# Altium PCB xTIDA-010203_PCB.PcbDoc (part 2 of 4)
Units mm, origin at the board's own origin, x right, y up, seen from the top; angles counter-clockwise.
Board outline 200 x 130 mm, 4 copper layers (Top Layer, Signal Layer 1, Signal Layer 2, Bottom Layer), stack 1.588 mm thick; 249 components, 140 nets, 768 pads, 520 vias.
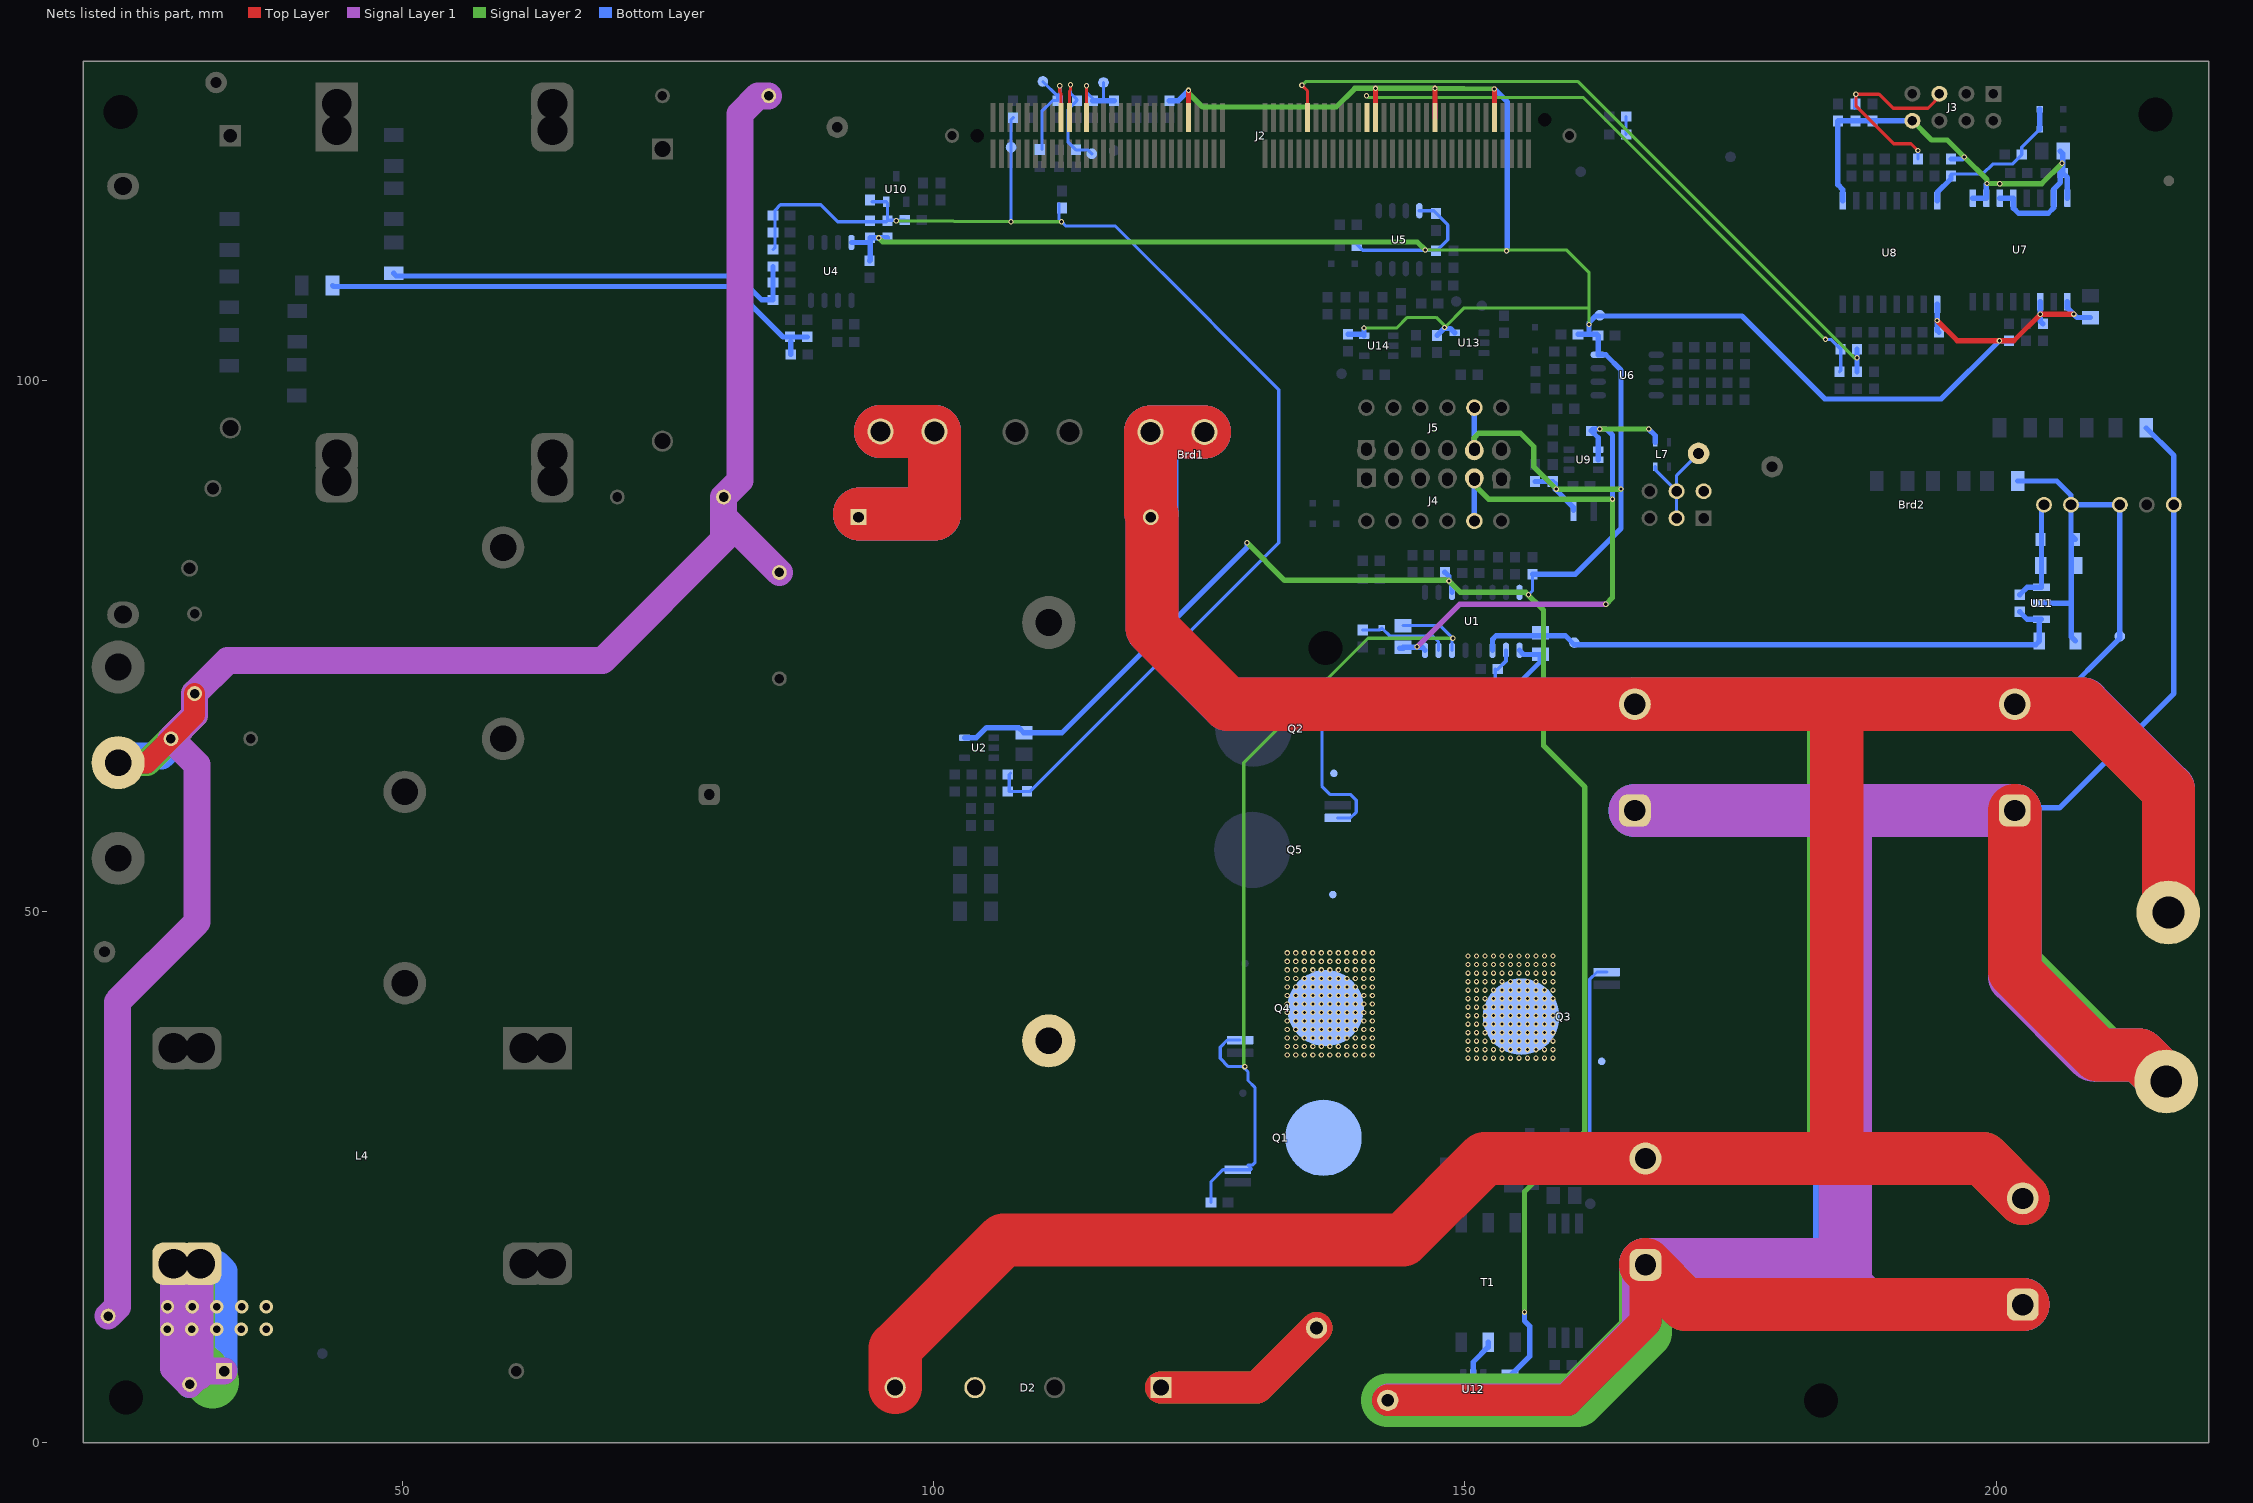
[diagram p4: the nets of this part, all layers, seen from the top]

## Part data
Brd1: library part "Brd- GaN", "GaN daughter card with LMG342xR030", Manufacturer="TEXAS INSTRUMENTS"
Brd2: "60W AuxPower", Manufacturer="Texas Instrument"
C1 C2 C3 C4: library part CMP-0084882-1, "CAP, AL, 680 μF, 450 V, +/- 20%, TH", Cap_Case=35x57mm, Manufacturer=Rubycon, Supplier Part Number 1=1189-2666-ND, Tolerance_%=20%, Value2=450V, ValueDisplayed=680μF
C5: library part CMP-0012436-3, "CAP, Film, 2.2 uF, 630 V, +/- 20%, TH", Manufacturer=Panasonic, Tolerance_%=20%, Value1=Unknown, Value2=630V, ValueDisplayed=2.2uF
C6: library part CMP-0007022-5, "CAP, CERM, 4.7 uF, 35 V, +/- 10%, X5R, 0603", Cap_Case=0603, Manufacturer=TDK, Supplier Part Number 1=445-9064-1-ND, TempCo=X5R, Tolerance_%=10%, Value1="0.003728 ohm", Value2=35V, ValueDisplayed=4.7uF
C7 C14: library part CMP-0009608-4, "CAP, CERM, 330 pF, X1 250 VAC/Y2 300 VAC, +/- 10%, B, TH", Cap_Case=7x5x10mm, Manufacturer=MuRata, Supplier Part Number 1=490-9443-ND, TempCo=B, Tolerance_%=10%, Value1=Unknown, ValueDisplayed=330pF
C8 C9 C13 C15: library part CMP-0009596-2, "CAP, CERM, 1500 pF,  V, +/- 20%, E, D8xT6mm", Cap_Case=8x6x12mm, Manufacturer=TDK, Supplier Part Number 1=445-174536-ND, TempCo=E, Tolerance_%=20%, Value1=Unknown, Value2=V, ValueDisplayed=1500pF
C10 C11 C12: library part CMP-0012433-1, "CAP, Film, 1.2 uF, 630 V, +/- 10%, 0.017 ohm, TH", Manufacturer="Wurth Elktronik", Supplier Part Number 1=495-1886-ND, Tolerance_%=10%, Value1="0.017 ohm", Value2=630V, ValueDisplayed=1.2uF
C16 C26: library part CMP-0007071-1, "CAP, CERM, 22 pF, 50 V, +/- 5%, C0G/NP0, AEC-Q200 Grade 1, 0603", Cap_Case=0603, Manufacturer=TDK, Supplier Part Number 1=445-5632-1-ND, TempCo=C0G/NP0, Tolerance_%=5%, Value1=Unknown, Value2=50V, ValueDisplayed=22pF
C17 C22 C25 C48 C51: library part CMP-0008378-2, "CAP, CERM, 10 uF, 25 V, +/- 10%, X5R, 0805", Cap_Case=0805, Manufacturer=MuRata, Supplier Part Number 1=490-10748-2-ND, TempCo=X5R, Tolerance_%=10%, Value1=Unknown, Value2=25V, ValueDisplayed=10uF
C18: library part CMP-0006942-1, "CAP, CERM, 4700 pF, 50 V, +/- 5%, X7R, 0603", Cap_Case=0603, Manufacturer=Kemet, Supplier Part Number 1=399-1088-1-ND, TempCo=X7R, Tolerance_%=5%, Value1=Unknown, Value2=50V, ValueDisplayed=4700pF
C19: library part CMP-0008378-1, "CAP, CERM, 10 uF, 25 V, +/- 10%, X7R, 0805", Cap_Case=0805, Manufacturer=MuRata, Supplier Part Number 1=81-GRM21BZ71E106KE5L, TempCo=X7R, Tolerance_%=10%, Value1=Unknown, Value2=25V, ValueDisplayed=10uF
C20 C21 C27: library part CMP-0007432-5, "CAP, CERM, 1000 pF, 50 V, +/- 10%, X7R, 0603", Cap_Case=0603, Manufacturer=MuRata, Supplier Part Number 1=490-5768-2-ND, TempCo=X7R, Tolerance_%=10%, Value1=Unknown, Value2=50V, ValueDisplayed=1000pF
C23 C29: "CAP, CERM, 0.01uF, 50V, +/-10%, X7R, 0603", Cap_Case=0603, Manufacturer=Kemet, Supplier Part Number 1=399-5346-1-ND, TempCo=X7R, Tolerance_%=10, Value1=Unknown, Value2=50V, ValueDisplayed=0.01μF
C24 C32 C34 C35 C40 C46 C47 C49 C50 C64 C65 C66 C68: "CAP, CERM, 0.1 μF, 25 V,+/- 10%, X7R, 0603", Cap_Case=0603, Manufacturer=MuRata, Supplier Part Number 1=490-1524-1-ND, TempCo=X7R, Tolerance_%=10, Value2=25V, ValueDisplayed=0.1μF
C28 C59: "CAP, CERM, 1uF, 6.3V, +/-10%, X5R, 0603", Cap_Case=0603, Manufacturer=MuRata, Supplier Part Number 1=81-GRM185R60J105KE26, TempCo=X5R, Tolerance_%=10, Value1=Unknown, Value2=6.3V, ValueDisplayed=1μF
C30 C31 C33 C36 C37 C39 C42 C43: "CAP, CERM, 1000 pF, 50 V,+/- 10%, X7R, 0603", Cap_Case=0603, Manufacturer=MuRata, Supplier Part Number 1=490-1494-1-ND, TempCo=X7R, Tolerance_%=10, Value2=50V, ValueDisplayed=1000pF
C38: library part CMP-0007455-4, "CAP, CERM, 470 pF, 50 V, +/- 10%, X7R, 0603", Cap_Case=0603, Manufacturer=MuRata, Supplier Part Number 1=490-1489-1-ND, TempCo=X7R, Tolerance_%=10%, Value1=Unknown, Value2=50V, ValueDisplayed=470pF
C41 C45: library part GRM188R71E104KA01D, "CAP, CERM, 0.1 μF, 25 V,+/- 10%, X7R, 0603", Cap_Case=0603, Manufacturer=MuRata, Supplier Part Number 1=490-1524-1-ND, TempCo=X7R, Tolerance_%=10, Value2=25V
C44: library part CMP-0007346-2, "CAP, CERM, 0.47 uF, 25 V, +/- 10%, X5R, 0603", Cap_Case=0603, Manufacturer=MuRata, Supplier Part Number 1=GRM188R61E474KA12D-ND, TempCo=X5R, Tolerance_%=10%, Value1=Unknown, Value2=25V, ValueDisplayed=0.47uF
C52 C53: library part CMP-0007433-4, "CAP, CERM, 0.01 uF, 50 V, +/- 10%, X7R, 0603", Cap_Case=0603, Manufacturer=MuRata, Supplier Part Number 1=490-1512-1-ND, TempCo=X7R, Tolerance_%=10%, Value1=Unknown, Value2=50V, ValueDisplayed=0.01uF
C54 C55: "CAP, CERM, 1uF, 25V, +/-10%, X7R, 0603", Cap_Case=0603, Manufacturer=TDK, Supplier Part Number 1=445-5956-1-ND, TempCo=X7R, Tolerance_%=10, Value1=Unknown, Value2=25V, ValueDisplayed=1uF
C56: library part CMP-0007039-5, "CAP, CERM, 0.1 uF, 25 V, +/- 10%, X7R, 0603", Cap_Case=0603, Manufacturer=TDK, Supplier Part Number 1=445-1316-1-ND, TempCo=X7R, Tolerance_%=10%, Value1=Unknown, Value2=25V, ValueDisplayed=0.1uF
C57 C62 C63: library part CMP-0007005-1, "CAP, CERM, 22 uF, 10 V, +/- 20%, X5R, 0603", Cap_Case=0603, Manufacturer=TDK, Supplier Part Number 1=445-9077-1-ND, TempCo=X5R, Tolerance_%=20%, Value1="0.00371 ohm", Value2=10V, ValueDisplayed=22uF
C58: library part CMP-0007347-1, "CAP, CERM, 4.7 uF, 25 V, +/- 10%, X5R, 0603", Cap_Case=0603, Manufacturer=MuRata, Supplier Part Number 1=490-7203-1-ND, TempCo=X5R, Tolerance_%=10%, Value1=Unknown, Value2=25V, ValueDisplayed=4.7uF
C60 C61: library part CMP-0008655-2, "CAP, CERM, 33 uF, 25 V, +/- 20%, X5R, 1206", Cap_Case=1206_180, Manufacturer=TDK, Supplier Part Number 1=445-8046-1-ND, TempCo=X5R, Tolerance_%=20%, Value1="0.002648 ohm", Value2=25V, ValueDisplayed=33uF
C67: library part CMP-0008020-2, "CAP, CERM, 4.7 uF, 16 V, +/- 10%, X7R, AEC-Q200 Grade 1, 0805", Cap_Case=0805, Manufacturer=MuRata, Supplier Part Number 1=490-5332-1-ND, TempCo=X7R, Tolerance_%=10%, Value1=Unknown, Value2=16V, ValueDisplayed=4.7uF
D1 D3 D4 D5 D6 D7 D9 D10: library part BAS316,115, "Diode, Ultrafast, 100 V, 0.25 A, SOD-323", Manufacturer=Toshiba, Value1=0.25A, Value2=1.4V
D2: "Diode, Switching-Bridge, 800 V, 25 A, TH", Manufacturer=Shindengen, Supplier Part Number 1=627-D25XB60-7000, Value1=3.5A, Value2=1.05V
D8: library part CMP-0005747-4, "Diode, Zener, 18 V, 700 mW, SOD-123", Manufacturer=Toshiba, Power_W=700mW, Value1=0.7W
D15: library part CMP-0089345-2, "Bridge Rectifier Single Phase Schottky 30V Surface Mount MBS", Digikey Part Number=1655-1883-1-ND, Forward Current=2A, Manufacturer=SMC, Max Surge Forward Current=50A, Operating Temperature Range="-55°C to +150°C", Peak Reverse Current=0.1mA, ValueDisplayed=28pF
D16: library part CMP-0005769-2, "Diode, Zener, 16 V, 500 mW, AEC-Q101, SOD-123", Manufacturer="Diodes Inc.", Power_W=500mW, Supplier Part Number 1=BZT52C16-FDICT-ND, Value1=0.5W
F1: "Fuse, 20 A, 250 VAC, 60 VDC, TH", Irating_A=20A, Manufacturer=Littelfuse, Supplier Part Number 1=F3336-ND
FID1 FID2 FID3: library part CMP-0077181-1, "Fiducial mark.  There is nothing to buy or mount.", Manufacturer=N/A
H1 H2 H9 H10 H11: library part CMP-0003617-1, "Machine Screw, Round, #4-40 x 1/4, Nylon, Philips panhead", Manufacturer="B&F Fastener Supply", Supplier Part Number 1=H542-ND
H5 H6 H12 H13: library part CMP-0003610-1, "Standoff, Hex, 0.5\"L #4-40 Nylon", Manufacturer=Keystone, Supplier Part Number 1=36-1902C-ND
J2: library part controlCARD-120HSEC, "C2000 controlCARD-120HSEC connector, SMT", Manufacturer=Samtec
J3: "Header, 4-Pin, Dual row,2.54mm", Manufacturer=Any
J4 J5: "Receptacle, 2.54mm, 6x1, Gold, TH", Color=Black, Manufacturer=Molex, Supplier Part Number 1=WM18605-ND
L1: library part CHOKE_PQ35, "PFC CHOKE 480uH 33A", Manufacturer=Sunlord
L2 L5: "DM CHOKE", Manufacturer=Sunlord
L3: library part INDUCTOR_COUPLED_14_23, "Coupled inductor, 2x 1.01 mH, 2 x 0.0022ohm, 1650V TH", Manufacturer=Sunlord, ValueDisplayed=1mH
L4: library part CMP-0013122-2, "Coupled inductor, 2x 1.6 mH, 2 x 0.0022ohm, 1650V TH", Manufacturer=Sunlord, ValueDisplayed=1.6mH
L6: library part CMP-0063086-1, "Inductor, Wirewound, Ferrite, 10 uH, 0.68 A, 0.46 ohm, SMD", Manufacturer="Würth Elektronik", Value1="0.843 ohm", Value2=0.6A, ValueDisplayed=10uH
L7: "Coupled inductor, 0.2 A, 0.45 ohm, SMD", Manufacturer=TDK, Supplier Part Number 1=445-8930-1-ND
LBL1: library part CMP-0003625-1, "Thermal Transfer Printable Labels, 0.650\" W x 0.200\" H - 10,000 per roll", Manufacturer=Brady, Supplier Part Number 1=97C5133
Logo1: library part CMP-0074838-1, "Texas Instrument Corporate Signature"
LOGO2 LOGO4: library part CMP-0074837-1, "IEC 61010-1 Hot Surface Warning"
LOGO3 LOGO5: library part CMP-0074835-1, "IEC 61010-1 High Voltage Warning"
Logo6: library part CMP-0074847-1, "FCC_disclaimer"
Logo7: library part CMP-0074769-1
Logo8: library part CMP-0074844-1
Q1 Q2 Q4 Q5: library part CMP-0086487-1, "MOSFET N-CH 600V 67A 8HSOF", Manufacturer=Infineon
Q3: library part CMP-0086487-1, "MOSFET N-CH 650V 23A HSOF-8", Manufacturer=Infineon
R1 R3 R5 R6 R7 R8 R9 R10 R11 R22 R23 R24: library part CMP-0017798-2, "RES SMD 1M OHM 1% 1/4W 1206", Manufacturer="Vishay Dale", Power_W=250mW, Supplier Part Number 1=BC2834CT-ND, TempCo="100 ppm/C", Tolerance_%=1%, Value2=0.25W, Value_Code=1M00, ValueDisplayed=1.00M
R2 R12: library part CMP-0022735-5, "RES, 100 k, 1%, 0.1 W, 0603", Manufacturer=Yageo, Power_W=100mW, Supplier Part Number 1=311-100KHRCT-ND, TempCo="100 ppm/C", Tolerance_%=1%, Value2=0.1W, Value_Code=100k
R4 R13 R74 R75 R76 R99 R100 R101 R102 R103 R104 R105: library part CMP-0023198-5, "RES, 100R, 1%, 0.1 W, 0603", Manufacturer=Yageo, Power_W=100mW, TempCo="100 ppm/C", Tolerance_%=1%, Value2=0.1W, Value_Code=100R
R14 R16 R31 R64: library part CMP-0022684-3, "RES, 10.0 k, 1%, 0.1 W, 0603", Manufacturer=Panasonic, Power_W=100mW, Supplier Part Number 1=P10.0KHCT-ND, TempCo="100 ppm/C", Tolerance_%=1%, Value2=0.1W, Value_Code=10k0, ValueDisplayed=10.0k
R15 R17 R18: library part CRCW1206330KJNEA, "RES SMD 330K OHM 1% 1/4W 1206", Manufacturer=Yageo, Power_W=0.25, Supplier Part Number 1=RV1206FR-07330KL-ND, TempCo="200 ppm/C", Tolerance_%=5, Value1=5%, Value2=0.25W, Value_Code=330k
R19 R20 R21: library part CMP-0018570-2, "RES, 0.01, 1%, 1 W, 1206", Manufacturer=Vishay-Dale, Power_W=1W, Supplier Part Number 1=WSLP-.01CT-ND, TempCo="75 ppm/C", Tolerance_%=1%, Value_Code=R010, ValueDisplayed=0.01
R25 R36 R39 R41 R43 R44 R69 R70: "RES, 10.0 k, 1%, 0.1 W, 0603", Manufacturer=Vishay-Dale, Power_W=0.1, Supplier Part Number 1=541-10.0KHCT-ND, TempCo="100 ppm/C", Tolerance_%=1, Value1=1%, Value2=0.1W, Value_Code=10k0, ValueDisplayed=10.0k
R26 R27 R29 R30 R42 R48 R54 R60 R66 R78 R93 R94 R95: library part CMP-0022680-4, "RES, 1.00 k, 1%, 0.1 W, 0603", Manufacturer=Panasonic, Power_W=100mW, Supplier Part Number 1=P1.00KHCT-ND, TempCo="100 ppm/C", Tolerance_%=1%, Value2=0.1W, Value_Code=1k00, ValueDisplayed=1.00k
R28: "RES, 50, 1%, 0.1 W, 0603", Manufacturer=Vishay-Dale, Power_W=0.1, Supplier Part Number 1=89M6778, TempCo="100 ppm/C", Tolerance_%=1, Value1=1%, Value2=0.1W, Value_Code=50R0, ValueDisplayed=50
R32: library part CMP-0023168-5, "RES, 51.1, 1%, 0.1 W, 0603", Manufacturer=Yageo, Power_W=100mW, Supplier Part Number 1=311-51.1HRCT-ND, TempCo="100 ppm/C", Tolerance_%=1%, Value2=0.1W, Value_Code=51R1, ValueDisplayed=51.1
R33 R91: library part CMP-0022632-1, "RES, 88.7 k, 1%, 0.1 W, 0603", Manufacturer=Vishay-Dale, Power_W=100mW, Supplier Part Number 1=541-88.7KHCT-ND, TempCo="100 ppm/C", Tolerance_%=1%, Value2=0.1W, Value_Code=88k7, ValueDisplayed=88.7k
R35 R77 R83 R84 R85 R88 R89 R90: library part CMP-0023334-5, "RES, 9.31 k, 1%, 0.1 W, 0603", Manufacturer=Yageo, Power_W=100mW, Supplier Part Number 1=311-9.31KHRCT-ND, TempCo="100 ppm/C", Tolerance_%=1%, Value2=0.1W, Value_Code=9k31, ValueDisplayed=9.31k
R37: library part CMP-0023166-5, "RES, 51.1 k, 1%, 0.1 W, 0603", Manufacturer=Yageo, Power_W=100mW, Supplier Part Number 1=311-51.1KHRCT-ND, TempCo="100 ppm/C", Tolerance_%=1%, Value2=0.1W, Value_Code=51k1, ValueDisplayed=51.1k
R40 R45: library part CMP-0022692-1, "RES, 22.0 k, 1%, 0.1 W, AEC-Q200 Grade 0, 0603", Manufacturer=Panasonic, Power_W=100mW, Supplier Part Number 1=P22.0KHCT-ND, TempCo="100 ppm/C", Tolerance_%=1%, Value2=0.1W, Value_Code=22k0, ValueDisplayed=22.0k
R46: library part CMP-0023148-5, "RES, 4.30 k, 1%, 0.1 W, 0603", Manufacturer=Yageo, Power_W=100mW, Supplier Part Number 1=311-4.30KHRCT-ND, TempCo="100 ppm/C", Tolerance_%=1%, Value2=0.1W, Value_Code=4k30, ValueDisplayed=4.30k
R47: library part CMP-0022708-3, "RES, 7.50 k, 1%, 0.1 W, 0603", Manufacturer=Panasonic, Power_W=100mW, Supplier Part Number 1=P7.50KHCT-ND, TempCo="100 ppm/C", Tolerance_%=1%, Value2=0.1W, Value_Code=7k50, ValueDisplayed=7.50k
R49: "RES, 21.5k ohm, 1%, 0.1W, 0603", Manufacturer=Vishay-Dale, Power_W=0.1, Supplier Part Number 1=541-21.5KHCT-ND, TempCo="100 ppm/C", Tolerance_%=1, Value1=1%, Value2=0.1W, Value_Code=21k5
R50: library part CMP-0022680-4, "RES, 100 k, 1%, 0.1 W, 0603", Manufacturer=Panasonic, Power_W=100mW, TempCo="100 ppm/C", Tolerance_%=1%, Value2=0.1W
R52 R55 R61 R63: library part CMP-0022109-3, "RES, 1.00 k, 1%, 0.1 W, 0603", Manufacturer=Vishay-Dale, Power_W=100mW, Supplier Part Number 1=541-1.00KHCT-ND, TempCo="100 ppm/C", Tolerance_%=1%, Value2=0.1W, Value_Code=1k00, ValueDisplayed=1.00k
R53 R62: "RES, 43.0 k, 1%, 0.1 W, 0603", Manufacturer="Yageo America", Power_W=0.1, Supplier Part Number 1=311-43.0KHRCT-ND, TempCo="200 ppm/C", Tolerance_%=1, Value1=1%, Value2=0.1W, Value_Code=43k0, ValueDisplayed=43.0k
R57: library part CMP-0023108-4, "RES, 430 k, 1%, 0.1 W, 0603", Manufacturer=Yageo, Power_W=100mW, Supplier Part Number 1=311-430KHRCT-ND, TempCo="100 ppm/C", Tolerance_%=1%, Value2=0.1W, Value_Code=430k
R58 R68: library part CMP-0022680-4, "RES, 2.2 k, 1%, 0.1 W, 0603", Manufacturer=Panasonic, Power_W=100mW, TempCo="100 ppm/C", Tolerance_%=1%, Value2=0.1W, Value_Code=2k2
R65: library part CMP-0022906-5, "RES, 20.0 k, 1%, 0.1 W, 0603", Manufacturer=Yageo, Power_W=100mW, Supplier Part Number 1=311-20.0KHRCT-ND, TempCo="100 ppm/C", Tolerance_%=1%, Value2=0.1W, Value_Code=20k0, ValueDisplayed=20.0k
R71: library part CMP-0023198-5, "RES, 0, 1%, 0.1 W, 0603", Manufacturer=Yageo, Power_W=100mW, TempCo="100 ppm/C", Tolerance_%=1%, Value2=0.1W, Value_Code=0, ValueDisplayed=0R
R72 R79 R80 R81 R82 R86 R87: library part CMP-0023198-5, "RES, 5.10 k, 1%, 0.1 W, 0603", Manufacturer=Yageo, Power_W=100mW, Supplier Part Number 1=311-5.10KHRCT-ND, TempCo="100 ppm/C", Tolerance_%=1%, Value2=0.1W, Value_Code=5k10, ValueDisplayed=5.10k
R73: library part CMP-0023198-5, "RES, 100 k, 1%, 0.1 W, 0603", Manufacturer=Yageo, Power_W=100mW, TempCo="100 ppm/C", Tolerance_%=1%, Value2=0.1W, Value_Code=100k
R92: library part CMP-0022220-1, "RES, 22.1 k, 1%, 0.1 W, 0603", Manufacturer=Vishay-Dale, Power_W=100mW, Supplier Part Number 1=541-22.1KHCT-ND, TempCo="100 ppm/C", Tolerance_%=1%, Value2=0.1W, Value_Code=22k1, ValueDisplayed=22.1k
R96: library part CMP-0023309-5, "RES, 8.45 k, 1%, 0.1 W, 0603", Manufacturer=Yageo, Power_W=100mW, Supplier Part Number 1=311-8.45KHRCT-ND, TempCo="100 ppm/C", Tolerance_%=1%, Value2=0.1W, Value_Code=8k45, ValueDisplayed=8.45k
R97: library part CMP-0023153-5, "RES, 4.70 k, 1%, 0.1 W, 0603", Manufacturer=Yageo, Power_W=100mW, Supplier Part Number 1=311-4.70KHRCT-ND, TempCo="100 ppm/C", Tolerance_%=1%, Value2=0.1W, Value_Code=4k70, ValueDisplayed=4.70k
R98: library part CMP-0025885-5, "RES, 0, 5%, 0.1 W, 0603", Manufacturer=Yageo, Power_W=100mW, Supplier Part Number 1=311-0.0GRCT-ND, TempCo="200 ppm/C", Tolerance_%=5%, Value2=0.1W, Value_Code=0000, ValueDisplayed=0
RT1: library part B59751B0120A070, "Thermistor NTC, 50 ohm, 25%, D23 x T10mm, P7.8mm", Manufacturer=Ametherm, Supplier Part Number 1=570-1117-ND, Tolerance_%=25
RV1: "Varistor 275V RMS 10MM Radial, TH", Manufacturer="EPCOS Inc", Supplier Part Number 1=495-1433-ND
T1: library part CMP-0030623-1, "Transformer, 105uH, TH", Manufacturer="Wurth Elektronik", ValueDisplayed=105uH
TP1: library part CMP-0055138-1, "Test Point, Miniature, Black, TH", Color=Black, Manufacturer=Keystone, Supplier Part Number 1=36-5001-ND
TP2 TP3: library part CMP-0055137-1, "Test Point, Miniature, Red, TH", Color=Red, Manufacturer=Keystone, Supplier Part Number 1=36-5000-ND
TP4 TP5: library part CMP-0055141-1, "Test Point, Miniature, Yellow, TH", Color=Yellow, Manufacturer=Keystone, Supplier Part Number 1=36-5004-ND
TP6 TP7: library part CMP-0055141-1, "Test Point, Miniature, Yellow, TH", Color=Yellow, Manufacturer=Keystone, PartNumber=5004, Supplier Part Number 1=36-5004-ND
TP8 TP9 TP10 TP11 TP12 TP13: library part 0312-0-15-15-34-27-10-0, "Pin Receptacle, .032-.046\" .075\" Dia, Gold, TH", Manufacturer=Mill-Max, Supplier Part Number 1=0312-015153427100-ND
U1: library part CMP-0013026-3, "4-A, 6-A, 3.0-kVRMS Isolated Dual-Channel Gate Driver, D0016A (SOIC-16)", Alternate Manufacturer="Texas Instruments", PartNumber=UCC21222D
U2: library part CMP-0861047-2, "50-MHz, Low-Power, Gain of 6-V/V Stable, Rail-to-Rail Output CMOS Operational Amplifier, DBV0005A (SOT-23-5)", Alternate Manufacturer="Texas Instruments"
U3: library part CMP-0081091-1, "5-kVRMS, 3-A Single Channel Isolated Gate Driver with Opto Compatible Input, DWY0006A (SOIC-6)", Alternate Manufacturer="Texas Instruments"
U4: library part CMP-0068313-2, "Low Power Dual Operational Amplifier, 8-pin Narrow SOIC", Manufacturer="Texas Instruments"
U5: library part CMP-0065423-1, "4.5ns Rail-to-Rail Comparator, D0008A (SOIC-8)", Alternate Manufacturer="Texas Instruments"
U6: library part CMP-0068313-2, "Low Power Dual Operational Amplifier, 8-pin Narrow SOIC", Manufacturer="Texas Instruments", PartNumber=LM358B
U7: library part CMP-0081958-3, "500 mW, High-Efficiency, Low-Emissions, 5 kVRMS Isolated DC-DC Converter, DVE0016A (SO-MOD-16)", Alternate Manufacturer="Texas Instruments", Alternate PartNumber=UCC12050DVE, Operating Temperature Range="-40 to 125 C"
U8: library part CMP-0078433-2, "High Speed, Robust EMC, Reinforced Six-Channel Digital Isolator, DW0016B (SOIC-16)", Alternate Manufacturer="Texas Instruments", Alternate PartNumber=ISO7763DW, Operating Temperature Range="-55 to 125 C", Rating=Catalog
U9: library part CMP-0065097-1, "4V to 36 V 0.6 A Synchronous Step-Down Converter, DBV0006A (SOT-23-6)", Alternate Manufacturer="Texas Instruments", Alternate PartNumber=TPS560430XDBVT
U10: library part CMP-0033012-1, "Low-Voltage Adjustable Precision Shunt Regulator, 15 mA, -40 to 125 degC, 3-pin SOT-23 (DBZ), Green (RoHS & no Sb/Br)", Manufacturer="Texas Instruments", Rating=Catalog, Temp Coeff(Max)(ppm/ degree C)=129
U11: library part CMP-0074738-2, "3 Pin 100mA Fixed 12V Positive Voltage Regulator, PK0003A (SOT-3)", Alternate Manufacturer="Texas Instruments"
U12: library part CMP-0076095-1, "Low-Noise 1 A, 420 kHz Transformer Driver, DBV0006A (SOT-23-6)", Alternate Manufacturer="Texas Instruments", Alternate PartNumber=SN6505BDBVT
U13 U14: library part CMP-0051320-2, "Single Power Supply, Single BUFFER GATE w/ 3-State Output (active low enable), DBV0005A (SOT-23-5)", F @ Nom Voltage(Max)(Mhz)=50, Generic Part Number=SN74LV1T125, ICC @ Nom Voltage(Max)(mA)=0.01, Manufacturer="Texas Instruments", Operating Temperature Range="-40 to 125 C", Rating=Catalog, tpd @ Nom Voltage(Max)(ns)=14.5,9.5,8.0,6.5, Voltage(Nom)(V)=1.8,2.5,3.3,5.5

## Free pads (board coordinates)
  round 5 hole 2.5: 1(23.283,55) 1(23.283,64) 1(23.283,73)
  rrect50% 2x2 hole 1: 1(78.9,61)
  round 1 smd far side: 1(107.3,121.9) 2(110.3,128.1) 2(114.9,121.3) 2(116,128) 2(117,121.6) 2(138.4,100.6) 2(149.2,107.4) 2(151.6,107) 2(157.4,27.3) 2(160.304,75.3) 2(160.9,119.6) 2(161.8,22.5) 2(162.7,106.1) 2(211.637,75.9)
  rect 0.24x0.6 hole 0.7: 1(140.74,90.806) 2(140.74,93.346) 3(143.28,93.346) 4(143.28,90.806) 5(153.44,93.346) 6(153.44,90.806)

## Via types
v1: diameter 0.5, hole 0.3, Top Layer to Bottom Layer, tented both sides, 429 vias
v2: diameter 1.27, hole 0.711, Top Layer to Bottom Layer, tented both sides, 90 vias
v3: diameter 0.5, hole 0.3, Top Layer to Bottom Layer, 1 vias

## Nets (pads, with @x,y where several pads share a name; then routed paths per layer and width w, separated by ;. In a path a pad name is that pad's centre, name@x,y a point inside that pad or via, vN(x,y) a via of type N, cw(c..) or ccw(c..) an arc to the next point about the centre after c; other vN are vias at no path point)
1V65-ref: C16.1 C33.2 C59.1 C62.1 C63.1 pad.1@107.3,121.9 R25.2 R45.2 R69.2 R70.1 R93.2 R94.2 R95.2 U10.2 | length 126.4
  Signal Layer 2 w0.3: v1(96.5,115) v1(107.3,114.907) 108.193,114.907 108.2,114.9 v1(112.056,114.9)
  Bottom Layer w0.3: R45.2@84.9,112.283 85.1,112.483 85.1,116 85.6,116.5 89.4,116.5 91,114.9 95.581,114.9 R95.2@95.664,114.983 ; C59.1@94.216,116.776 U10.2@95.555,116.776 95.664,116.667 R95.2@95.664,114.983 ; v1(96.5,115) 97.3,115 R94.2@97.3,115.047 95.727,115.047 R95.2@95.664,114.983 ; C16.1@107.245,63 107.126,62.881 107.126,61.314 107.141,61.3 C62.1@108.8,61.3 109.116,61.3 132.5,84.684 132.5,99.102 126.472,105.13 126.472,105.139 125.711,105.901 125.701,105.901 117.102,114.5 112.456,114.5 v1(112.056,114.9) 111.8,115.156 R70.1@111.8,116.6 ; v1(107.3,114.907) 107.3,124.5 R69.2@107.5,124.7
5V_ISO: Brd2.2
5Vc: Brd1.10 C22.2 C28.1 C29.1 C32.2 C35.2 C40.2 C48.1 C49.2 C54.2 C57.1 C66.1 C67.1 C68.1 J2.48 J2.84 J2.98 J2.112 J5.5 L6.2 pad.2@162.7,106.1 R46.2 R50.1 R64.2 R72.2 R73.2 R91.2 R93.1 R95.1 T1.2 U1.3 U1.8 U2.5 U4.8 U5.8 U6.8 U7.1 U7.3 U8.1 U12.2 U12.5 U13.5 U14.5 | length 465.1
  Top Layer w0.5: J2.48@124,124.7 v1(124,127.26) ; J2.84@141.6,124.7 141.6,127.11 v1(141.6,127.45) ; J2.98@147.2,124.7 147.2,127.4 v1(147.2,127.45) ; v1(152.778,127.4) 152.8,127.378 J2.112@152.8,124.7 ; v1(194.445,105.6) 196.345,103.7 v1(200.3,103.7) 201.655,103.7 v1(204.155,106.2) 204.164,106.209 v1(207.3,106.209)
  Signal Layer 2 w0.3: v1(140.522,104.9) 143.6,104.9 144.6,105.9 147.3,105.9 148.1,105.1 v1(148.1,104.949) 149.942,106.791 161.62,106.791 161.679,106.85 ; v1(146.286,112.235) 159.595,112.235 161.679,110.151 161.679,106.85 ; v1(161.679,105.224) 161.679,106.85
  Signal Layer 2 w0.5: v1(94.855,113.383) 95.239,113 145.521,113 v1(146.286,112.235) ; v1(124,127.26) 124,127.01 124.51,126.5 124.52,126.5 125.32,125.7 137.9,125.7 139.65,127.45 v1(141.6,127.45) v1(147.2,127.45) v1(152.778,127.4) ; v1(129.5,84.7) 133.048,81.152 v1@148.5,81.152 ; v1(148.5,81.1) 149.575,80.025 155.725,80.025 157.4,78.35 157.4,65.6 161.3,61.7 161.3,29.3 155.622,23.622 v1(155.622,12.3) ; Brd1.10@150.9,93.346 J5.5@150.9,93.596 150.9,94.6 151.3,95 155.231,95 156.5,93.731 156.5,91.839 v1(158.6,89.739) 164.689,89.739 v1(164.7,89.75)
  Bottom Layer w0.3: R64.2@139.753,112.872 140.402,112.222 147.412,112.222 148.399,113.21 148.399,114.608 147.069,115.938 U5.8@145.717,115.938 ; U1.8@155.145,80.025 155.725,80.025 155.95,79.8 v1(156,79.8) 156.371,80.171 C29.1@156.371,81.736
  Bottom Layer w0.5: U4.8@92.285,112.95 R93.1@94.047,112.95 ; C32.2@94,111.225 94.047,111.272 R93.1@94.047,112.95 ; R95.1@95.664,113.383 v1(94.855,113.383) R93.1@94.047,113.383 R93.1@94.047,112.95 ; U2.5@102.925,66.35 104.05,66.35 105,67.3 108.016,67.3 C22.2@108.5,66.816 112.087,66.816 129.5,84.229 v1(129.5,84.7) ; R72.2@122.2,126.3 123.04,126.3 v1(124,127.26) ; C68.1@139,104.32 140.387,104.32 U14.5@140.522,104.185 v1(140.522,104.9) ; C66.1@147.4,104.199 148.05,104.849 148.65,104.849 U13.5@149.05,104.449 ; C28.1@148.121,81.92 148.5,81.54 v1(148.5,81.1) 148.795,80.805 U1.3@148.795,80.025 ; U12.5@150.797,3.678 150.797,5.353 ; Brd1.10@150.9,93.346 J5.5@150.9,93.596 J5.5@150.9,97.406 ; T1.2@152.2,9.48 152.2,9 150.797,7.597 U12.2@150.797,6.428 150.797,5.353 ; v1(152.778,127.4) 154.006,126.172 154.006,112.242 v1(153.923,112.159) ; v1(155.622,12.3) 155.622,11.478 156.1,11 156.1,8.116 C67.1@154.253,6.269 153.337,5.353 150.797,5.353 ; C29.1@156.371,81.736 160.4,81.736 164.7,86.036 v1(164.7,89.75) 164.7,100.946 163.264,102.382 U6.8@162.547,102.382 162.547,104.194 C40.2@162.529,104.212 162.441,104.3 161.7,104.3 ; R91.2@156.608,90.462 C57.1@158.27,90.462 158.5,90.232 158.5,89.75 158.511,89.739 v1(158.6,89.739) 158.6,89.65 160.229,88.021 L6.2@160.229,87.762 ; R46.2@160.65,104.3 161.7,104.3 ; U8.1@194.445,107.125 v1(194.445,105.6) 194.445,104.681 C54.2@194.625,104.501 ; R73.2@201.2,103.701 v1(200.3,103.7) 194.824,98.224 183.876,98.224 176.073,106.027 162.309,106.027 161.679,105.397 v1(161.679,105.224) 161.679,104.321 161.7,104.3 ; U7.3@204.155,107.375 v1(204.155,106.2) 204.155,105.534 C49.2@204.4,105.289 ; U7.1@206.695,107.375 206.695,106.803 207.614,105.884 C48.1@208.866,105.884
5Vcomm: C55.2 D7.1 D9.1 R35.1 U8.16 | length 15.3
  Bottom Layer w0.3: C55.2@195.745,119.4 198.734,119.4 199.659,120.325 201.523,120.325 R35.1@202.415,121.217 202.415,121.916 D9.1@204.1,123.601
  Bottom Layer w0.5: U8.16@194.445,116.875 194.445,117.645 195.745,118.945 C55.2@195.745,119.2 ; D9.1@204.1,123.601 D7.1@204.1,125.5
12V_B-: Brd2.11 C60.1 D8.1 R98.1 U11.3 | length 10.2
  Bottom Layer w0.5: R98.1@202.216,79.8 202.916,80.5 U11.3@204.266,80.5 204.266,88.036 Brd2.11@204.5,88.27
12V_ISO: Brd2.3 Brd2.4 L7.4 TP7.1 | length 10.1
  Bottom Layer w0.3: L7.4@167.922,91.85 167.922,91.549 Brd2.4@169.931,89.54 ; Brd2.3@169.931,87 Brd2.4@169.931,89.54 ; TP7.1@172,93.1 169.931,91.031 Brd2.4@169.931,89.54
12V_L: C25.1 C61.1 pad.2@160.304,75.3 R98.2 U1.11 U11.1 | length 57.5
  Bottom Layer w0.5: U1.11@152.605,74.575 152.605,75.6 152.958,75.953 159.447,75.953 160.3,75.1 203.721,75.1 C61.1@204.066,75.445 U11.1@204.066,77.5 ; R98.2@202.216,78.2 202.916,77.5 U11.1@204.066,77.5 ; U11.1@204.266,77.5 U11.1@204.066,77.5
12Vc: Brd1.9 C17.1 C58.1 J4.2 L7.1 U1.16 U9.4 U9.5 | length 67.8
  Signal Layer 1 w0.5: v1(145.5,74.9) 149.5,78.9 v1(163.269,78.9)
  Signal Layer 2 w0.5: Brd1.9@150.9,90.806 J4.2@150.9,90.556 150.9,90.128 152.228,88.8 v1(163.9,88.8) 163.9,79.531 v1(163.269,78.9) ; v1(162.7,95.4) v1(167.3,95.4)
  Bottom Layer w0.5: C17.1@143.873,74.768 C17.1@144.2,74.768 ; C17.1@144.2,74.868 145.962,74.868 U1.16@146.255,74.575 ; J4.2@150.9,86.746 J4.2@150.9,90.556 Brd1.9@150.9,90.806 ; U9.5@162.554,92.512 U9.4@162.554,93.462 162.554,94.579 C58.1@161.904,95.229 162.076,95.4 v1(162.7,95.4) 163.331,95.4 163.9,94.831 v1(163.9,88.8) ; v1(167.3,95.4) 167.922,94.778 L7.1@167.922,94.15
+BRDG_N: D1.1 R4.1 U1.15 | length 8.5
  Bottom Layer w0.3: R4.1@140.4,76.49 142.011,76.49 D1.1@142.197,76.677 142.974,75.9 147,75.9 147.525,75.375 U1.15@147.525,74.575
+BRDG_P: D3.1 R13.1 U1.10 | length 3.5
  Bottom Layer w0.35: R13.1@152.875,72.8 152.875,71.525 D3.1@153,71.4 ; R13.1@153.1,72.8 153.875,73.575 U1.10@153.875,74.575
-BRDG_N: C17.2 Q1.2 Q4.2 R2.1 U1.14 | length 82.2
  Signal Layer 2 w0.3: v1(129.301,35.4) 129.2,35.501 129.2,64.006 140.894,75.7 v1(148.876,75.7)
  Bottom Layer w0.3: R2.1@126.113,22.6 126.113,24.575 127.238,25.7 Q1.2@128.65,25.7 129.846,25.7 129.919,25.773 129.6,26.093 129.6,26.15 130.045,26.15 130.25,26.355 130.25,33.445 129.6,34.095 129.6,34.9 129.1,35.4 127.755,35.4 126.983,36.173 126.983,37.227 127.655,37.9 Q4.2@128.85,37.9 ; C17.2@144.2,76.9 147.676,76.9 v1(148.876,75.7) 148.795,75.619 U1.14@148.795,74.575
-BRDG_P: C25.2 Q2.2 Q5.2 R12.1 U1.9 | length 40.2
  Bottom Layer w0.3: Q5.2@138.05,58.8 139.245,58.8 139.79,59.345 139.79,60.479 139.269,61 137.35,61 136.55,61.8 136.55,69.85 136.9,70.2 Q2.2@138.15,70.2
  Bottom Layer w0.5: Q2.2@138.15,70.2 140.448,70.2 R12.1@140.9,69.748 141.252,70.1 153.7,70.1 157.1,73.5 C25.2@157.1,74.184 155.536,74.184 U1.9@155.145,74.575
AC-L: C9.1 C11.1 D2.3 L1.2 L4.3 | length 55.2
  Signal Layer 1 w2.54: L4.3@28.5,16.85 28.5,7 C9.1@30,5.5 31,6.5 ; 31,6.3 31,6.5 ; L4.3@31,16.85 31,6.5 ; C11.1@33.25,6.75 31.25,6.75 31,6.5
  Signal Layer 2 w5: L4.3@29.9,15.45 29.9,8 31.2,6.7 32.15,5.75
  Bottom Layer w2.54: L4.3@28.5,16.85 L4.3@31,16.85 32.588,16.85 33.25,16.188 C11.1@33.25,6.75 31.25,6.75 C9.1@30,5.5
  other v2: 27.9,10.7 30.225,10.7 32.55,10.7 34.875,10.7 37.2,10.7 27.925,12.809 30.25,12.809 32.575,12.809 34.9,12.809 37.225,12.809
ACL_SENSE: C36.1 R11.2 R43.1 R44.2 | length 39.9
  Bottom Layer w0.5: R11.2@49.2,110.05 49.45,109.8 81.6,109.8 83.844,107.556 R44.2@84.9,107.556 C36.1@84.9,109.166 R43.1@84.9,110.674
ACN_SENSE: C31.1 R24.2 R39.1 R41.2 | length 47.9
  Bottom Layer w0.5: R24.2@43.45,108.9 43.55,108.8 81.1,108.8 85.838,104.062 C31.1@86.515,104.062 R41.2@88.125,104.062 ; R39.1@86.564,102.4 C31.1@86.564,103.626
AGND-s: C50.2 C51.1 C55.1 J3.8 R83.1 R84.1 R85.1 U7.9 U7.10 U7.11 U7.12 U7.15 U7.16 U8.9 | length 51.4
  Signal Layer 2 w0.5: J3.8@192.12,124.4 193.92,122.6 195.4,122.6 v1(197,121) 199.13,118.87 v1(199.13,118.5) 200.322,118.5 v1(200.345,118.477) 204.277,118.477 v1(206.2,120.4)
  Bottom Layer w0.5: U8.9@185.555,116.875 185.555,117.935 185.1,118.39 R85.1@185.1,124.38 185.12,124.4 J3.8@192.12,124.4 ; C55.1@195.745,120.8 196.8,120.8 v1(197,121) ; U7.9@197.805,117.125 U7.10@199.075,117.125 199.075,118.445 v1(199.13,118.5) ; U7.11@200.345,117.125 U7.12@201.615,117.125 201.615,116.185 202.1,115.7 204.9,115.7 205.425,116.225 U7.15@205.425,117.125 205.425,117.99 206.035,118.6 206.035,119.685 C50.2@206.25,119.9 ; C51.1@206.016,121.55 206.25,121.316 C50.2@206.25,119.9 ; U7.16@206.695,117.125 206.695,119.055 C50.2@206.25,119.5 C50.2@206.25,119.9
ANA_Iac: C18.2 J2.18 pad.2@110.3,128.1 R28.2 | length 12
  Top Layer w0.3: v1(111.876,127.7) 111.876,127.1 112,126.977 J2.18@112,124.7
  Bottom Layer w0.3: R28.2@110.2,121.7 110.2,125.3 111.2,126.3 C18.2@111.7,126.3 111.7,126.7 C18.2@111.65,126.75 ; pad.2@110.3,128.1 C18.2@111.65,126.75 ; v1(111.876,127.7) 111.876,126.977 C18.2@111.65,126.75
ANA_Vac: C34.2 J2.20 pad.2@114.9,121.3 R42.1 | length 11.8
  Top Layer w0.3: J2.20@112.8,124.7 112.8,127.191 112.9,127.291 v1(112.9,127.8)
  Bottom Layer w0.3: v1(112.9,127.8) 112.9,127.191 112.9,127.009 113.5,126.409 C34.2@113.5,126.3 112.675,125.475 112.675,122.389 R42.1@113.4,121.664 114.536,121.664 pad.2@114.9,121.3
ANA_Vdc: C44.2 J2.24 pad.2@116,128 R60.1 | length 8.6
  Top Layer w0.3: J2.24@114.4,124.7 v1(114.4,127.7)
  Bottom Layer w0.3: v1@114.5,127.8 v1(114.4,127.7) 114.4,127.1 C44.2@115.2,126.3 ; 116,126.3 pad.2@116,128
  Bottom Layer w0.5: C44.2@115,126.3 115.2,126.3 116,126.3 R60.1@117,126.3
B1+: Brd1.20 Brd1.21 C5.1 D2.1 Q1.9 Q3.9 Q4.9 RT1.1 TP8.1 TP9.1 | length 113.6
  Top Layer w3: D2.1@121.4,5.2 130.45,5.2 RT1.1@136.05,10.8
  Top Layer w5: C5.1@93.05,87.4 100.1,87.4 TP9.1@100.1,95.175 TP8.1@95.02,95.175
  Signal Layer 1 w5: C5.1@93.05,87.4 100.1,87.4 TP9.1@100.1,95.175 TP8.1@95.02,95.175
  Signal Layer 2 w3: D2.1@121.4,5.2 130.45,5.2 RT1.1@136.05,10.8
  Signal Layer 2 w5: C5.1@93.05,87.4 100.1,87.4 TP9.1@100.1,95.175 TP8.1@95.02,95.175
  Bottom Layer w5: C5.1@93.05,87.4 100.1,87.4 TP9.1@100.1,95.175 TP8.1@95.02,95.175
  other v1: 150.3,36.2 151.1,36.2 151.9,36.2 152.7,36.2 153.5,36.2 154.3,36.2 155.1,36.2 155.9,36.2 156.7,36.2 157.5,36.2 158.3,36.2 133.3,36.5 134.1,36.5 134.9,36.5 135.7,36.5 136.5,36.5 137.3,36.5 138.1,36.5 138.9,36.5 139.7,36.5 140.5,36.5 141.3,36.5 150.3,37 151.1,37 151.9,37 152.7,37 153.5,37 154.3,37 155.1,37 155.9,37 156.7,37 157.5,37 158.3,37 133.3,37.3 134.1,37.3 134.9,37.3 135.7,37.3 136.5,37.3 137.3,37.3 138.1,37.3 138.9,37.3 139.7,37.3 140.5,37.3 141.3,37.3 150.3,37.8 151.1,37.8 151.9,37.8 152.7,37.8 153.5,37.8 154.3,37.8 155.1,37.8 155.9,37.8 156.7,37.8 157.5,37.8 158.3,37.8 133.3,38.1 134.1,38.1 134.9,38.1 135.7,38.1 136.5,38.1 137.3,38.1 138.1,38.1 138.9,38.1 139.7,38.1 140.5,38.1 141.3,38.1 150.3,38.6 151.1,38.6 151.9,38.6 152.7,38.6 153.5,38.6 154.3,38.6 155.1,38.6 155.9,38.6 156.7,38.6 157.5,38.6 158.3,38.6 133.3,38.9 134.1,38.9 134.9,38.9 135.7,38.9 136.5,38.9 137.3,38.9 138.1,38.9 138.9,38.9 139.7,38.9 140.5,38.9 141.3,38.9 150.3,39.4 151.1,39.4 151.9,39.4 152.7,39.4 153.5,39.4 154.3,39.4 155.1,39.4 155.9,39.4 156.7,39.4 157.5,39.4 158.3,39.4 133.3,39.7 134.1,39.7 134.9,39.7 135.7,39.7 136.5,39.7 137.3,39.7 138.1,39.7 138.9,39.7 139.7,39.7 140.5,39.7 141.3,39.7 150.3,40.2 151.1,40.2 151.9,40.2 152.7,40.2 153.5,40.2 154.3,40.2 155.1,40.2 155.9,40.2 156.7,40.2 157.5,40.2 158.3,40.2 133.3,40.5 134.1,40.5 134.9,40.5 135.7,40.5 136.5,40.5 137.3,40.5 138.1,40.5 138.9,40.5 139.7,40.5 140.5,40.5 141.3,40.5 150.3,41 151.1,41 151.9,41 152.7,41 153.5,41 154.3,41 155.1,41 155.9,41 156.7,41 157.5,41 158.3,41 133.3,41.3 134.1,41.3 134.9,41.3 135.7,41.3 136.5,41.3 137.3,41.3 138.1,41.3 138.9,41.3 139.7,41.3 140.5,41.3 141.3,41.3 150.3,41.8 151.1,41.8 151.9,41.8 152.7,41.8 153.5,41.8 154.3,41.8 155.1,41.8 155.9,41.8 156.7,41.8 157.5,41.8 158.3,41.8 133.3,42.1 134.1,42.1 134.9,42.1 135.7,42.1 136.5,42.1 137.3,42.1 138.1,42.1 138.9,42.1 139.7,42.1 140.5,42.1 141.3,42.1 150.3,42.6 151.1,42.6 151.9,42.6 152.7,42.6 153.5,42.6 154.3,42.6 155.1,42.6 155.9,42.6 156.7,42.6 157.5,42.6 158.3,42.6 133.3,42.9 134.1,42.9 134.9,42.9 135.7,42.9 136.5,42.9 137.3,42.9 138.1,42.9 138.9,42.9 139.7,42.9 140.5,42.9 141.3,42.9 150.3,43.4 151.1,43.4 151.9,43.4 152.7,43.4 153.5,43.4 154.3,43.4 155.1,43.4 155.9,43.4 156.7,43.4 157.5,43.4 158.3,43.4 133.3,43.7 134.1,43.7 134.9,43.7 135.7,43.7 136.5,43.7 137.3,43.7 138.1,43.7 138.9,43.7 139.7,43.7 140.5,43.7 141.3,43.7 150.3,44.2 151.1,44.2 151.9,44.2 152.7,44.2 153.5,44.2 154.3,44.2 155.1,44.2 155.9,44.2 156.7,44.2 157.5,44.2 158.3,44.2 133.3,44.5 134.1,44.5 134.9,44.5 135.7,44.5 136.5,44.5 137.3,44.5 138.1,44.5 138.9,44.5 139.7,44.5 140.5,44.5 141.3,44.5 150.3,45 151.1,45 151.9,45 152.7,45 153.5,45 154.3,45 155.1,45 155.9,45 156.7,45 157.5,45 158.3,45.004 133.3,45.3 134.1,45.3 134.9,45.3 135.7,45.3 136.5,45.3 137.3,45.3 138.1,45.3 138.9,45.3 139.7,45.3 140.5,45.3 141.3,45.304 150.3,45.8 151.1,45.8 151.9,45.8 152.7,45.8 153.5,45.8 154.3,45.8 155.1,45.8 155.9,45.8 156.7,45.8 157.5,45.8 158.3,45.8 133.3,46.1 134.1,46.1 134.9,46.1 135.7,46.1 136.5,46.1 137.3,46.1 138.1,46.1 138.9,46.1 139.7,46.1 140.5,46.1 141.3,46.1
B+: Brd2.7 C1.1 C2.1 C3.1 C4.1 Q3.3-4-5-6-7-8 R1.2 RT1.2 TP2.1 | length 590
  Top Layer w3: RT1.2@142.75,4 159.6,4 167,11.4 C2.1@167,16.75
  Top Layer w5: C2.1@167,16.75 170.75,13 C1.1@202.5,13 ; C3.1@201.75,59.5 201.75,44.35 209.6,36.5 213.5,36.5 TP2.1@216,34
  Signal Layer 1 w3: RT1.2@142.877,4.1 159.6,4.1 166.3,10.8 166.3,16.05 C2.1@167,16.75
  Signal Layer 1 w5: C4.1@166,59.5 185.1,59.5 ; C2.1@167,16.75 183.85,16.75 185.8,14.8 ; C1.1@202.5,13 187.6,13 185.8,14.8 ; TP2.1@216,34 213.5,36.5 209.1,36.5 201.75,43.85 C3.1@201.75,59.5 185.1,59.5 ; 185.1,59.5 185.8,58.8 185.8,14.8
  Signal Layer 2 w5: RT1.2@142.75,4 160.6,4 167,10.4 C2.1@167,16.75 170.75,13 C1.1@202.5,13 ; C3.1@201.75,59.5 201.75,45.05 210.3,36.5 213.5,36.5 TP2.1@216,34
  Bottom Layer w0.5: C3.1@201.75,59.5 202,59.75 205.95,59.75 216.717,70.517 Brd2.7@216.717,88.27 216.717,92.904 R1.2@214.122,95.5
  Bottom Layer w3: C2.1@166.1,15.85 C2.1@167,16.75
  Bottom Layer w5: C4.1@166,59.5 185.25,59.5 ; C2.1@167,16.75 184.25,16.75 185.25,15.75 ; C1.1@202.5,13 185.25,13 185.25,15.75 ; TP2.1@216,34 213.5,36.5 209.5,36.5 201.75,44.25 C3.1@201.75,59.5 185.25,59.5 ; 185.25,15.75 185.25,59.5
B-: Brd1.24 Brd1.25 Brd2.9 Brd2.10 C1.2 C2.2 C3.2 C4.2 C5.2 C60.2 C61.2 D2.4 D8.2 pad.2@211.637,75.9 Q2.3-4-5-6-7-8 Q5.3-4-5-6-7-8 R3.2 TP1.1 TP12.1 TP13.1 U11.2 | length 694.6
  Top Layer w5: D2.4@96.4,5.2 96.4,8.9 106.6,19.1 144.2,19.1 151.85,26.75 C2.2@167,26.75 185,26.75 ; TP13.1@125.5,95.124 TP12.1@120.42,95.124 120.42,87.53 120.55,87.4 120.55,76.677 127.727,69.5 C4.2@166,69.5 184.7,69.5 ; C1.2@202.5,23 198.75,26.75 185,26.75 ; TP1.1@216.2,49.9 216.2,61.4 208.1,69.5 C3.2@201.75,69.5 184.7,69.5 ; 184.7,69.5 185,69.2 185,26.75
  Signal Layer 1 w3: C5.2@120.42,87.53 C5.2@120.55,87.4
  Signal Layer 1 w5: C5.2@120.42,87.53 TP12.1@120.42,95.124 TP13.1@125.5,95.124 ; C5.2@120.55,87.4 120.55,76.65 127.7,69.5 C4.2@166,69.5 C3.2@201.75,69.5 208.2,69.5 216.2,61.5 TP1.1@216.2,49.9
  Signal Layer 2 w3: C5.2@120.55,87.4 120.42,87.53 TP12.1@120.42,95.124 TP13.1@125.5,95.124
  Signal Layer 2 w5: C4.2@166,69.5 185,69.5 ; C2.2@167,26.75 184.7,26.75 ; C1.2@202.5,23 198.75,26.75 184.7,26.75 ; TP1.1@216.2,49.9 216.2,61.4 208.1,69.5 C3.2@201.75,69.5 185,69.5 ; 184.7,26.75 184.7,69.2 185,69.5
  Bottom Layer w0.5: R3.2@202.03,90.5 205.7,90.5 207.04,89.16 Brd2.10@207.04,88.27 ; C3.2@202.5,69.5 205.415,69.5 211.637,75.722 pad.2@211.637,75.9 Brd2.9@211.637,88.27 Brd2.10@207.04,88.27 ; U11.2@204.316,79 207.069,79 ; D8.2@207.454,85 D8.2@207.069,85.384 ; C61.2@207.466,75.445 207.069,75.842 207.069,79 ; Brd2.10@207.04,88.27 207.04,85.414 D8.2@207.069,85.384 ; 207.069,79 D8.2@207.069,85.384
  Bottom Layer w3: C4.2@166,69.5 C3.2@201.75,69.5 C3.2@202.5,69.5
  Bottom Layer w5: C5.2@120.55,87.4 120.55,94.994 TP12.1@120.42,95.124 TP13.1@125.5,95.124
Debug_J3-1: C53.1 R78.1 | length 1.7
  Bottom Layer w0.3: R78.1@165.18,123.1 C53.1@165.18,124.8
DRV_RELAY: Q3.1 R31.2 R32.2 | length 20.7
  Bottom Layer w0.3: R32.2@160.519,25.316 R31.2@160.519,26.916 160.519,27.619 161.75,28.85 161.75,43.615 162.435,44.3 Q3.1@163.35,44.3
EARTH: C7.2 C8.2 C9.2 C13.1 C14.1 C15.1 pad.1@23.283,64 | length 199.6
  Top Layer w2: pad.1@23.283,64 26,64 C14.1@28.25,66.25 30.476,68.476 C7.2@30.476,70.5
  Signal Layer 1 w2.54: C9.2@22.34,11.928 23.2,12.788 23.2,41.5 30.691,48.991 30.691,63.809 C14.1@28.25,66.25 30.476,68.476 C7.2@30.476,70.5 33.576,73.6 68.85,73.6 80.25,85 80.25,87.15 ; C8.2@84.5,126.75 83.5,126.75 81.8,125.05 81.8,90.55 C15.1@80.25,89 80.25,87.15 ; C13.1@85.5,81.9 80.25,87.15
  Signal Layer 2 w2.54: pad.1@23.283,64 26,64 C14.1@28.25,66.25 30.476,68.476 C7.2@30.476,70.5
  Bottom Layer w2.54: pad.1@23.283,63.75 24.158,64.625 27.375,64.625 C14.1@28.625,65.875
FSI-RX0-Pri: J2.68 R86.2 R89.2 | length 68.5
  Top Layer w0.3: v1(134.669,127.743) 135.2,127.212 J2.68@135.2,124.7
  Signal Layer 2 w0.3: v1(134.669,127.743) 135.019,128.093 160.658,128.093 186.651,102.1 v1(186.9,102.1)
  Bottom Layer w0.5: R89.2@186.91,100.789 R86.2@186.91,102.901
FSI-RX0-Sec: J3.5 R80.1 R84.2 | length 20.4
  Top Layer w0.3: v1(192.632,121.6) 191.983,122.249 190.349,122.249 186.8,125.797 v1(186.8,126.9) 188.988,126.9 190.3,125.588 193.588,125.588 194.8,126.8 J3.5@194.66,126.94
  Bottom Layer w0.3: R84.2@186.662,125.588 R84.2@186.662,126.362 ; R84.2@186.762,125.98 186.762,126.862 v1(186.8,126.9) ; R80.1@192.632,120.8 v1(192.632,121.6)
FSI-RX1-Pri: J2.82 R87.2 R88.2 | length 56.7
  Signal Layer 2 w0.3: v1(140.74,126.75) 140.89,126.6 161.118,126.6 183.886,103.831 v1(183.945,103.831)
  Bottom Layer w0.3: v1(183.945,103.831) 184.436,103.831 R87.2@185.367,102.901 185.367,100.89 R88.2@185.25,100.774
